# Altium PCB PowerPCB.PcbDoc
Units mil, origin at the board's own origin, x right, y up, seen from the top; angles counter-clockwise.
Board outline 7150 x 4890 mil, 2 copper layers (Top Layer, Bottom Layer); 59 components, 37 nets, 220 pads, 65 vias.
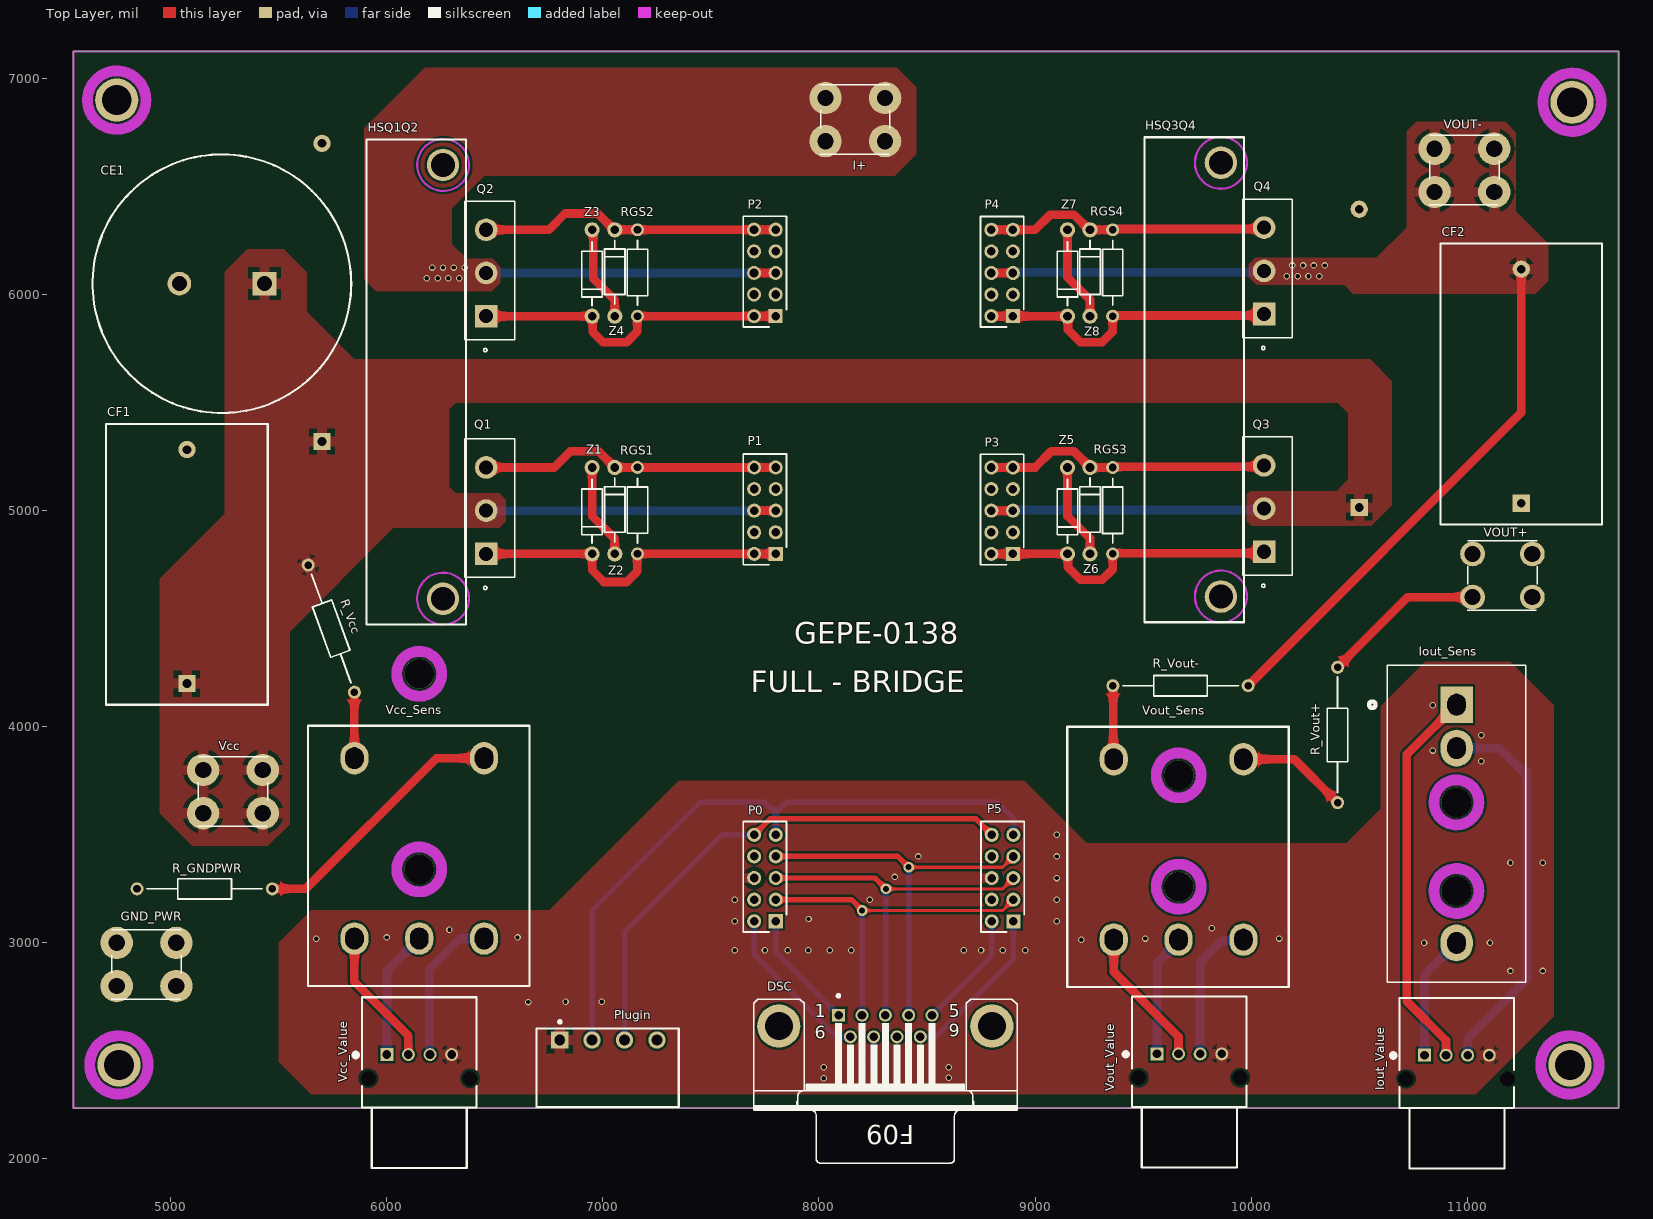
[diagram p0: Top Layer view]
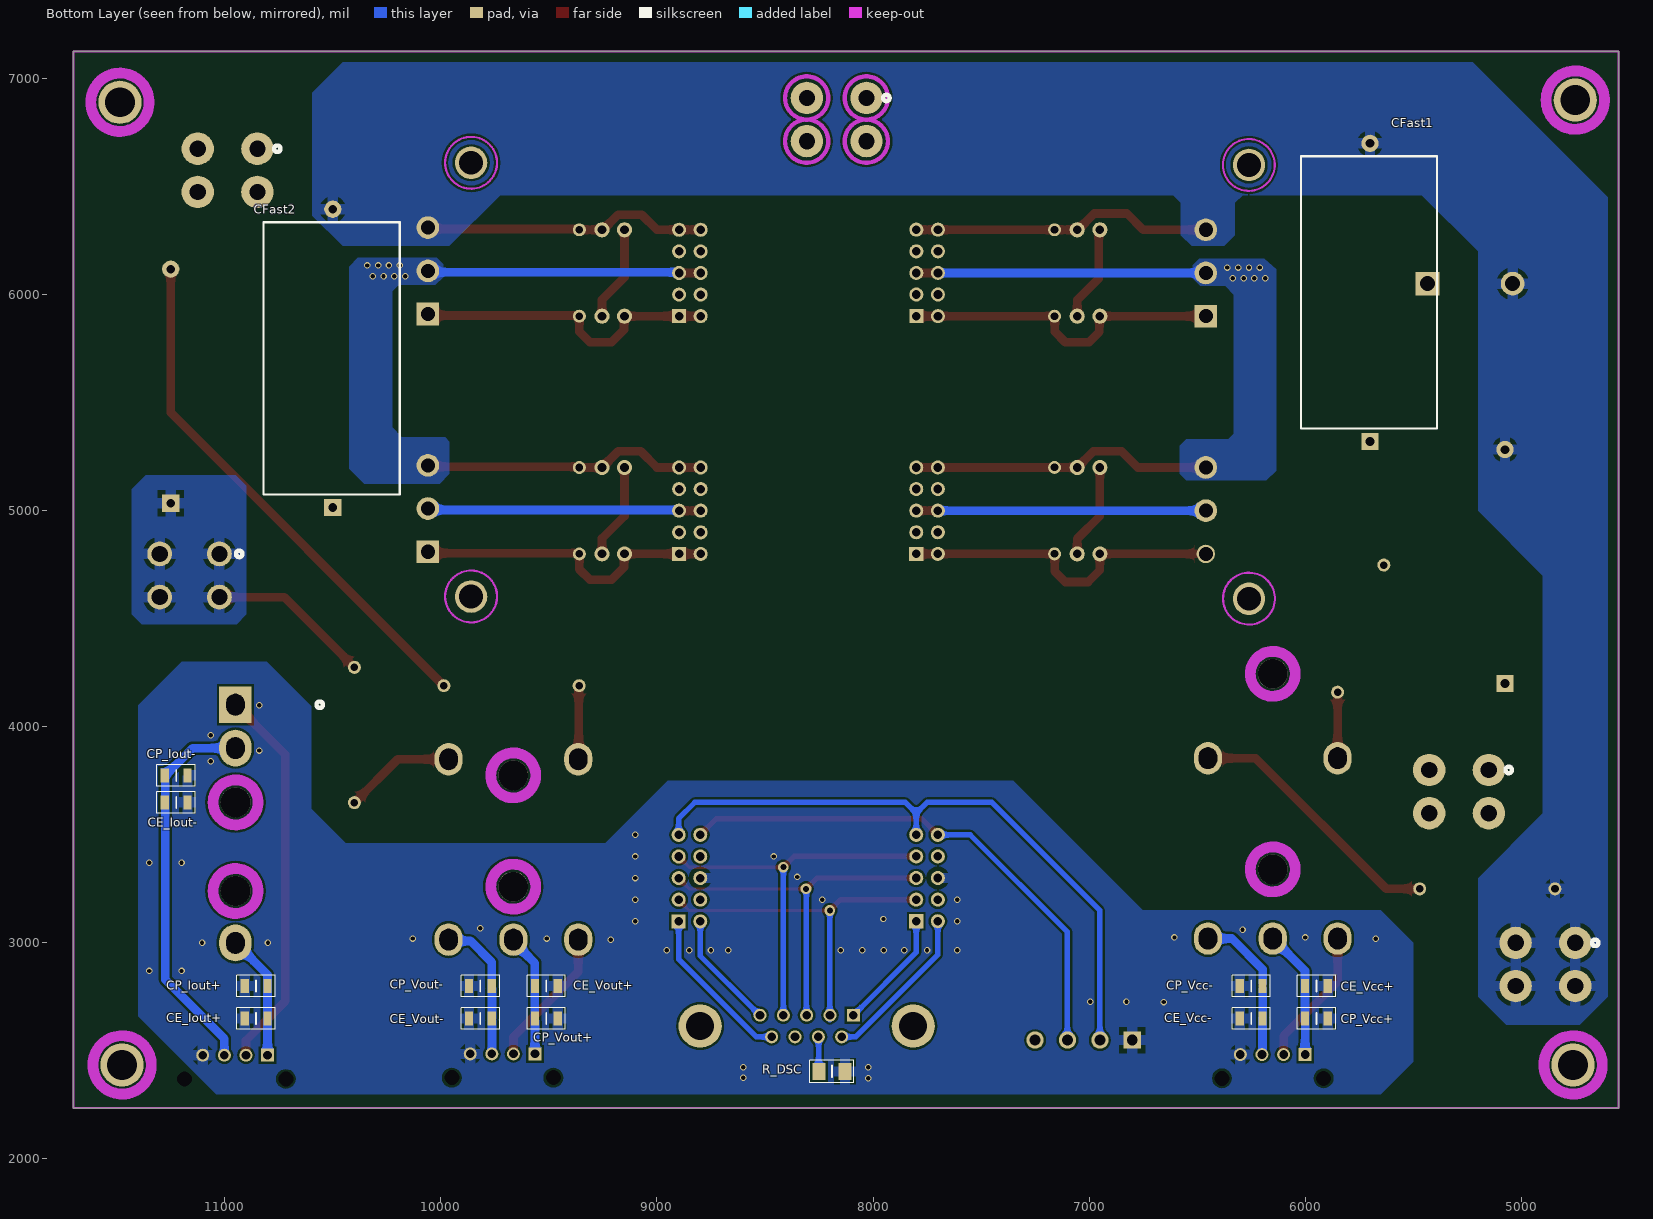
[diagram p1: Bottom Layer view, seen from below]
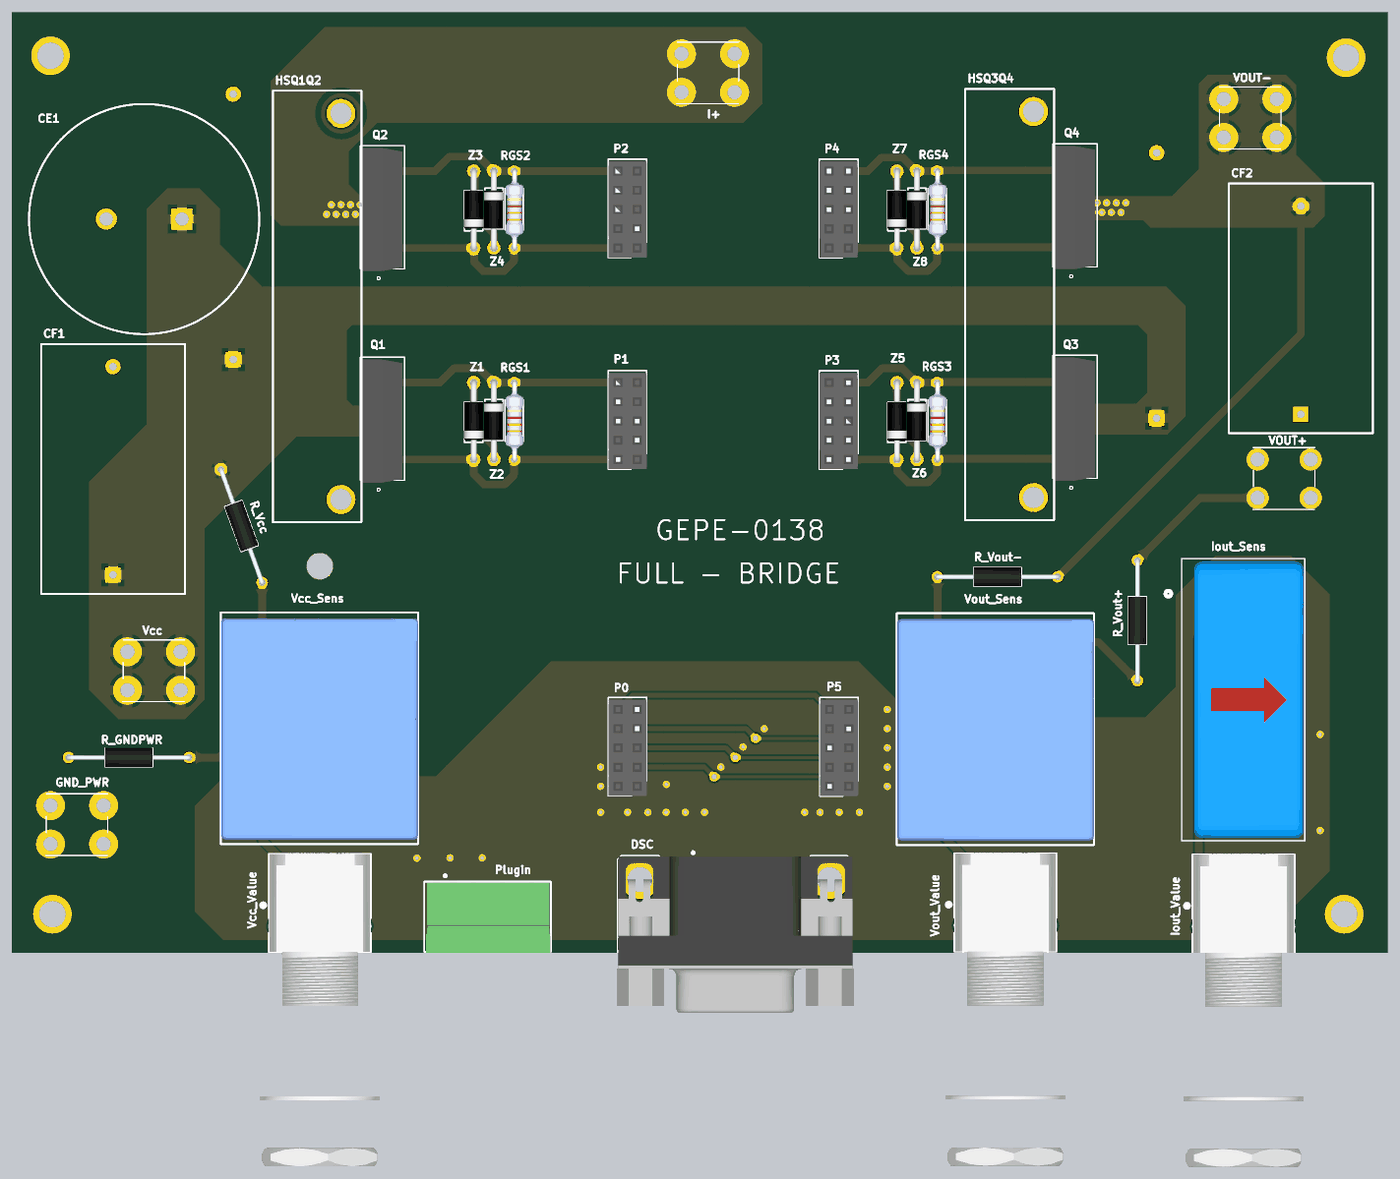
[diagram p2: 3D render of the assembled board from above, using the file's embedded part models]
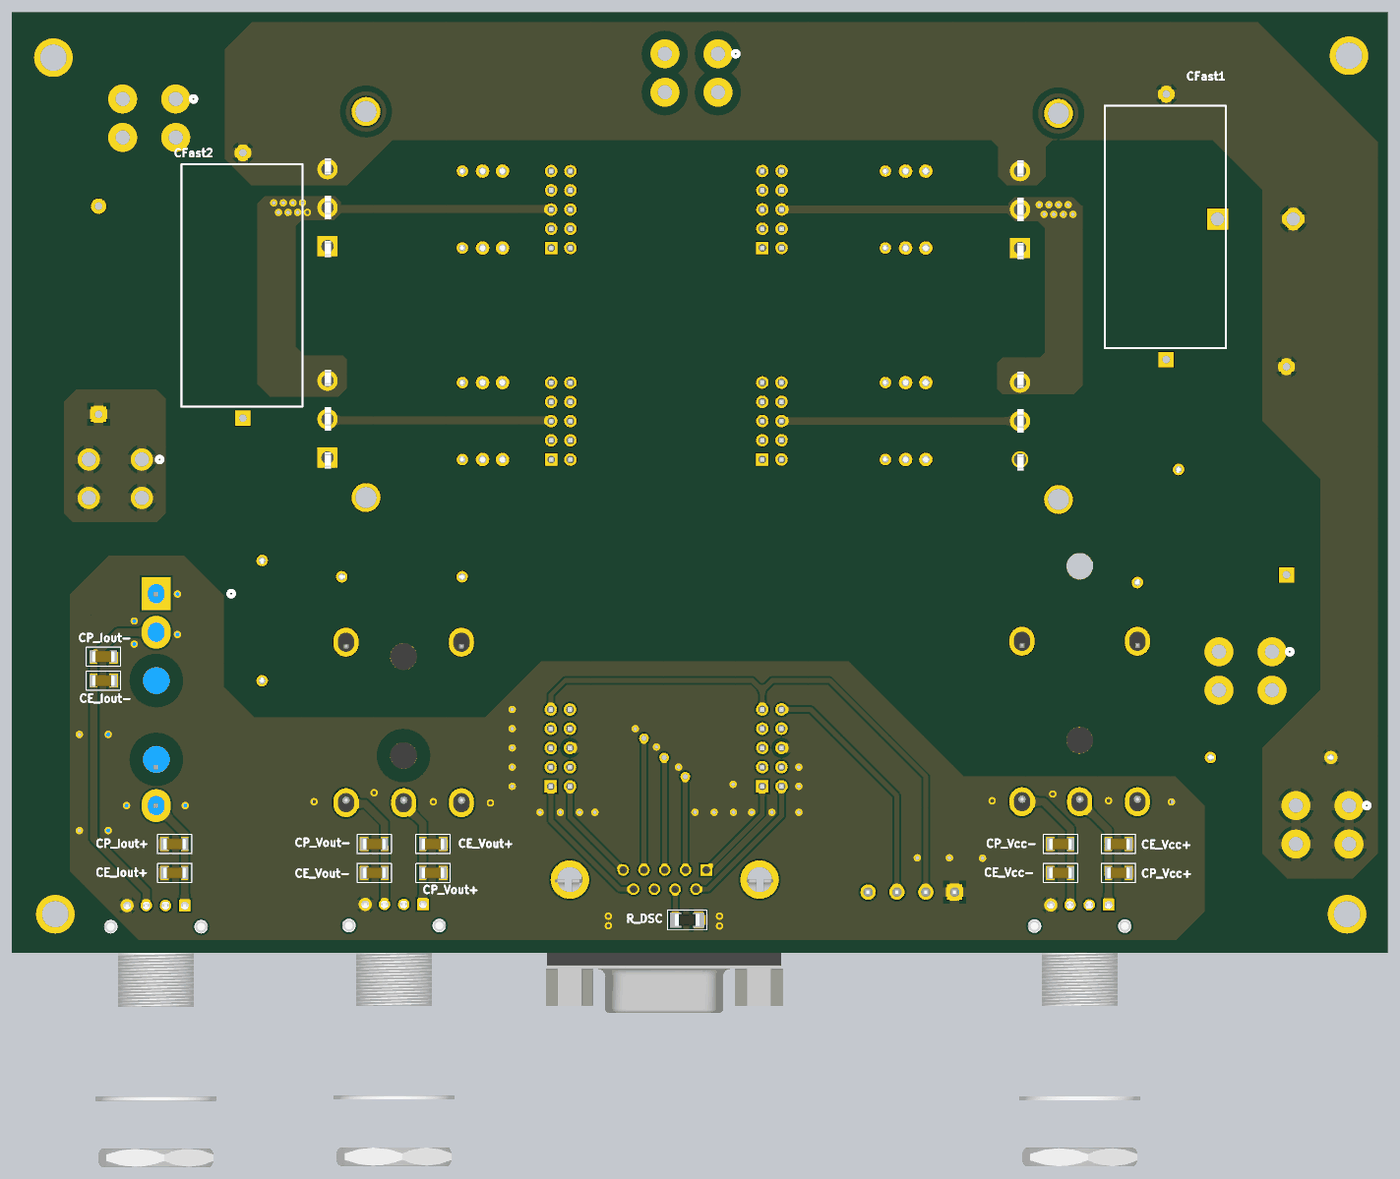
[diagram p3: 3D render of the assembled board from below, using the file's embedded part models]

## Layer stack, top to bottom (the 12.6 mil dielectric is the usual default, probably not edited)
Top Solder: solder mask 0.4, Solder Resist, Dk 3.5
Top Layer: signal copper 1.4
Dielectric 1: dielectric 12.6, FR-4, Dk 4.8
Bottom Layer: signal copper 1.4
Bottom Solder: solder mask 0.4, Solder Resist, Dk 3.5

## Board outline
4550,2235 11700,2235 11700,7125 4550,7125

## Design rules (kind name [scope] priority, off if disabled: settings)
Clearance Clearance_1 [All] p1: gap=10 ignorepadtopadclearanceinfootprint=TRUE
Clearance gnd_ISO_ [InNet('GND_ISO1') vs InNet('GND_PWR')] p2: gap=20 ignorepadtopadclearanceinfootprint=FALSE
ComponentClearance [All] p1: gap=-5 collisioncheckmode=3 verticalgap=-5 showdistances=FALSE
Height [All] p1: minheight=0 maxheight=5000 prefheight=2000
HoleSize [All] p1: absolutevalues=TRUE maxlimit=500 minlimit=1 maxpercent=80.000 minpercent=20.000
NetAntennae [All] p1: netantennaetolerance=10
PlaneClearance [All] p1: clearance=10
PolygonConnect [All] p1: connectstyle=Relief reliefconductorwidth=50 reliefentries=4 polygonreliefangle="90 Angle" airgapwidth=20
RoutingVias [All] p1: holewidth=28 width=50 viastyle="Through Hole" minholewidth=10 minwidth=10 maxholewidth=100 maxwidth=100
SilkToSilkClearance [All] p1: silktosilkclearance=5
SilkToSolderMaskClearance [IsPad] p1: minsilkscreentomaskgap=0 clearancetoexposedcopper=TRUE
SolderMaskExpansion [All] p1: expansion=4
Width [All] p1: maxlimit=180 minlimit=15 preferedwidth=40
23 further rules are at their usual default settings.

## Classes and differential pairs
component class Sensores: CE_Iout+ CE_Iout- CE_Vcc+ CE_Vcc- CE_Vout+ CE_Vout- CP_Iout+ CP_Iout- CP_Vcc+ CP_Vcc- CP_Vout+ CP_Vout- Iout_Sens R_GNDPWR R_Vcc R_Vout+ R_Vout- Vcc_Sens Vout_Sens
component class PowerPCB: CE1 CF1 CF2 CFast1 CFast2 DSC GND_PWR HSQ1Q2 HSQ3Q4 I+ Iout_Value P0 P1 P2 P3 P4 P5 Plugin Q1 Q2 Q3 Q4 R_DSC RGS1 RGS2 RGS3 RGS4 Vcc Vcc_Value VOUT+ VOUT- Vout_Value x Z1 Z2 Z3 Z4 Z5 Z6 Z7 Z8

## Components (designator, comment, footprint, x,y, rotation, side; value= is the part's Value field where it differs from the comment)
CE1 "CAP" CAP_ELETRO 5433.54,6050.5 r180 top
CE_Iout+ "CAP" CAP3115_SMD 10855,2650 r0 bottom
CE_Iout- "CAP" CAP3115_SMD 11225,3650 r180 bottom
CE_Vcc+ "CAP" CAP3115_SMD 5948,2800 r180 bottom
CE_Vcc- "CAP" CAP3115_SMD 6250,2650 r0 bottom
CE_Vout+ "CAP" CAP3115_SMD 9512,2800 r180 bottom
CE_Vout- "CAP" CAP3115_SMD 9817,2650 r0 bottom
CF1 "CAP" CAP_MKP1848C61050JK2 5075,4200 r90 top
CF2 "CAP" CAP_MKP1848C61050JK2 11250,5035 r90 top
CFast1 "CAP" CAP_FAST 5700,5320 r90 bottom
CFast2 "CAP" CAP_FAST 10500,5015 r90 bottom
CP_Iout+ "CAP" CAP3115_SMD 10855,2800 r0 bottom
CP_Iout- "CAP" CAP3115_SMD 11225,3775 r180 bottom
CP_Vcc+ "CAP" CAP3115_SMD 5948,2650 r180 bottom
CP_Vcc- "CAP" CAP3115_SMD 6250,2800 r0 bottom
CP_Vout+ "CAP" CAP3115_SMD 9512,2650 r180 bottom
CP_Vout- "CAP" CAP3115_SMD 9817,2800 r0 bottom
DSC "Con_DB9" CON_DB9_FEMALE 8520,2665 r0 top
GND_PWR "8191" CONN_8191_KEY#1 4750,3000 r0 top
HSQ1Q2 "Heat_Sinks_TO247" HEAT_SINKS_TO247 6260,4592.13 r90 top
HSQ3Q4 "Heat_Sinks_TO247" HEAT_SINKS_TO247 9860,4602.13 r90 top
I+ "8191" CONN_8191_KEY#1 8030,6910 r0 top
Iout_Sens "LA100P" LA100P 10950,4100 r0 top
Iout_Value "Con_MiniXLR_TRAPC4M" CON_MINIXLR_TRAPC4M1X 10802,2480 r0 top
P0 "Header 5X2" HEADER_FEM_TH_10P_2.54 7700,3100 r90 top
P1 "Header 5X2" HEADER_FEM_TH_10P_2.54 7699.85,4800.12 r90 top
P2 "Header 5X2" HEADER_FEM_TH_10P_2.54 7699.53,5900.26 r90 top
P3 "Header 5X2" HEADER_FEM_TH_10P_2.54 8797.44,4799.87 r90 top
P4 "Header 5X2" HEADER_FEM_TH_10P_2.54 8797.44,5900 r90 top
P5 "Header 5X2" HEADER_FEM_TH_10P_2.54 8799.44,3099.74 r90 top
Plugin "Con_4Pin_Horizontal_plugin_3.81mm" 691322310004 6800,2550 r0 top
Q1 "LSIC1MO120E0080" SICMOSFET#1 6460,4800 r90 top
Q2 "LSIC1MO120E0080" SICMOSFET#2 6460,5900 r90 top
Q3 "LSIC1MO120E0080" SICMOSFET#2 10060,4810 r90 top
Q4 "LSIC1MO120E0080" SICMOSFET#2 10060,5910 r90 top
R_DSC "Res1" RESIS_SMD_1206 8190,2405 r0 bottom
R_GNDPWR "Res1" RESIS_TH_15.9 4844.02,3250 r0 top
R_Vcc "Res1" RESIS_TH_15.9 5635.9,4748.23 r290 top
R_Vout+ "Res1" RESIS_TH_15.9 10400,4275 r270 top
R_Vout- "Res1" RESIS_TH_15.9 9985.98,4190 r180 top
RGS1 "Res1" RESIS_TH_10.1 7160,5200 r270 top
RGS2 "Res1" RESIS_TH_10.1 7160,6300 r270 top
RGS3 "Res1" RESIS_TH_10.1 9359.01,5199.75 r270 top
RGS4 "Res1" RESIS_TH_10.1 9359.01,6300 r270 top
Vcc "8191" CONN_8191_KEY#1 5150,3800 r0 top
Vcc_Sens "Volt_Sens" VOLT_SENS 5850,3020 r0 top
Vcc_Value "Con_MiniXLR_TRAPC4M" CON_MINIXLR_TRAPC4M1X 6000,2483 r0 top
VOUT+ "8191" CONN_8191_KEY#2 11025,4800 r0 top
VOUT- "8191" CONN_8191_KEY#1 10849,6675 r0 top
Vout_Sens "Volt_Sens" VOLT_SENS 9364,3015 r0 top
Vout_Value "Con_MiniXLR_TRAPC4M" CON_MINIXLR_TRAPC4M1X 9564,2486 r0 top
Z1 "TLHR5400-AS12Z" DIODE_TH_10.1 6950,4800 r90 top
Z2 "TLHR5400-AS12Z" DIODE_TH_10.1 7055,5200 r270 top
Z3 "TLHR5400-AS12Z" DIODE_TH_10.1 6950,5900 r90 top
Z4 "TLHR5400-AS12Z" DIODE_TH_10.1 7055,6300 r270 top
Z5 "TLHR5400-AS12Z" DIODE_TH_10.1 9150,4799.87 r90 top
Z6 "TLHR5400-AS12Z" DIODE_TH_10.1 9254,5199.87 r270 top
Z7 "TLHR5400-AS12Z" DIODE_TH_10.1 9150,5900 r90 top
Z8 "TLHR5400-AS12Z" DIODE_TH_10.1 9254,6300 r270 top

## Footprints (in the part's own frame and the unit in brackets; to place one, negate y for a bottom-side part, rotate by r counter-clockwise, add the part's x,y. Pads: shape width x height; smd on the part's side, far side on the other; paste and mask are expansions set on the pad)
691322310004 [mil] "WR-TBL Series 322 - 3.81 mm Horizontal PCB Header"
  rect 80x80 hole 50: 1(0,0)
  round 80 hole 50: 2(150,0) 3(300,0) 4(450,0)
  silkscreen extent -107,-310 551,91, body extent -97,-315 549,47, height 295
CAP3115_SMD [mm]
  rect 0.96x1.64 smd: 1(-1.34,0) 2(1.34,0)
  silkscreen extent -2.26,-1.25 2.25,1.25, body extent -1.55,-0.75 1.55,0.75, height 1.8
CAP_ELETRO [mil] "Nichicon_LGL"
  rect 110x110 hole 70: 1(0,0)
  round 110 hole 70: 2(393.7,0)
  silkscreen extent -402,-598 795,598, body extent -394,-590 787,590, height 984
CAP_FAST [mil] "LCR PC/HV/S/WF 100nF"
  rect 80x80 hole 40: 1(0,0)
  round 80 hole 40: 2(1380,0)
  silkscreen extent 60,-310 1320,320, body extent -20,-315 1400,325, height 670
CAP_MKP1848C61050JK2 [mil] "MKP1848C61050JK2"
  rect 80x80 hole 40: 1(0,0)
  round 80 hole 40: 2(1082.68,0)
  silkscreen extent -98,-374 1201,374, body extent -79,-354 1181,359, height 984
CON_DB9_FEMALE [mil] "Connector; D Subminiature; 9 Position; Right Angle; Pitch 1.385 mm"
  rect 60x60 hole 40: 1(-429,0)
  round 60 hole 40: 2(-321,0) 3(-213,0) 4(-105,0) 5(3,0) 6(-375,-100) 7(-267,-100) 8(-159,-100) 9(-51,-100)
  round 200 hole 130: 10(-706,-50) 10(280,-50)
  silkscreen extent -823,-684 398,96, body extent -825,-742 405,69, height 493
CON_MINIXLR_TRAPC4M1X [mil]
  rect 60x60 hole 40: 1(0,0)
  round 60 hole 40: 2(200,0) 3(300,0) 4(100,0)
  round 35 hole 70 unplated: MH1(-85,-110) MH2(385,-110)
  silkscreen extent -144,-525 415,265, body extent -162,-1359 462,271, height 105
CONN_8191_KEY#1 [mil]
  round 150 hole 75 mask+0: 1(0,0) 2(276,0) 3(0,-200) 4(276,-200)
  silkscreen extent -25,-260 298,62
CONN_8191_KEY#2 [mil]
  round 115 hole 75 mask+0: 1(0,0) 2(276,0) 3(0,-200) 4(276,-200)
  silkscreen extent -25,-260 298,62
DIODE_TH_10.1 [mil]
  round 70 hole 40: 1(0,0) 2(400,0)
  silkscreen extent 49,-47 345,47, body extent -15,-51 415,50, height 100
HEADER_FEM_TH_10P_2.54 [mil]
  rect 65x65 hole 40: 1(0,-100)
  round 65 hole 40: 2(0,0) 3(100,-100) 4(100,0) 5(200,-100) 6(200,0) 7(300,-100) 8(300,0) 9(400,-100) 10(400,0)
  silkscreen extent -50,-150 462,50, body extent -50,-150 450,50, height 335
HEAT_SINKS_TO247 [mm] "VRA-55-101E"
  round 3.81 hole 2.8 unplated: 1(0,0) 2(51,0)
  silkscreen extent -3,-2.7 54,9, body extent -3,-25 54,9, height 39.5
LA100P [mil]
  rect 150x170 hole 85 slot 100 at 90 deg mask+0: 1(0.58,2.07)
  oval 150x170 hole 85 slot 100 at 90 deg mask+0: 2(0.58,-198.71) 3(0.58,-1100.29)
  silkscreen extent -404,-1283 321,184, body extent -254,-1269 314,169, height 1085
RESIS_SMD_1206 [mil]
  rect 60x80 smd: 1(-60,0) 2(60,0)
  silkscreen extent -102,-52 102,52, body extent -63,-31 63,31, height 30
RESIS_TH_10.1 [mil]
  round 60 hole 35: 1(0,0) 2(400,0)
  silkscreen extent 50,-47 350,47, body extent -12,-45 412,49, height 95
RESIS_TH_15.9 [mil]
  round 60 hole 35: 1(0,0) 2(625.98,0)
  silkscreen extent 45,-47 580,47, body extent -12,-49 638,49, height 98
SICMOSFET#1 [mil]
  rect 105x105 / inner round 85 / far side round 85 hole 65 mask+0: 1(0,0)
  round 105 hole 65 mask+0: 2(200,0) 3(400,0)
  silkscreen extent -165,-131 532,99, body extent -120,-120 520,89, height 961
SICMOSFET#2 [mil]
  rect 105x105 hole 65 mask+0: 1(0,0)
  round 105 hole 65 mask+0: 2(200,0) 3(400,0)
  silkscreen extent -165,-131 532,99, body extent -120,-120 520,89, height 961
VOLT_SENS [mil]
  oval 130x150 hole 85 slot 100 at 90 deg: 1(0,834.6) 2(600,834.6) 3(0,0) 4(300,0) 5(600,0)
  silkscreen extent -215,-220 810,985, body extent -213,-195 811,954, height 658

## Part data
CE1 CE_Iout+ CE_Iout- CE_Vcc+ CE_Vcc- CE_Vout+ CE_Vout- CF1 CF2 CFast1 CFast2 CP_Iout+ CP_Iout- CP_Vcc+ CP_Vcc- CP_Vout+ CP_Vout-: "Capacitor", Manufacturer_Name=Kemet, Manufacturer_Part_Number=C1206X475K3RACAUTO7210, Mouser Part Number=80-C1206X475K3RAUTLR
DSC: "DB9 (Right angle  PCB mount)", ASiD Part Number=DB9-AS
GND_PWR I+ Vcc VOUT+ VOUT-: "No Description Available", Mfr_Name="Keystone Electronics"
Iout_Value Vcc_Value Vout_Value: "Connector", Arrow Part Number=TRAPC4M1X, Manufacturer_Name=Switchcraft, Mouser Part Number=502-TRAPC4M1X
P0 P1 P2 P3 P4 P5: library part Con_Header_10P, "Connector dual row"
Plugin: "691322310004 WE"
Q1 Q2 Q3 Q4: library part SICMOS
R_DSC R_GNDPWR R_Vcc R_Vout+ R_Vout- RGS1 RGS2 RGS3 RGS4: library part Resistor, "Resistor"
Z1 Z2 Z3 Z4 Z5 Z6 Z7 Z8: library part Diode, "Diode", Manufacturer_Name=Vishay

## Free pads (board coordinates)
  round 200 hole 137.8 mask+0: 1(4750,6900) 1(4760,2435) 1(11475,2435) 1(11485,6890)
  round 137.8 hole 137.8 mask+0: 1(6150,3340) 1(6150,4245) 1(9665,3260) 1(9665,3775) 1(10950,3240) 1(10950,3650)

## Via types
v1: diameter 30, hole 20, Top Layer to Bottom Layer, 62 vias
v2: diameter 50, hole 28, Top Layer to Bottom Layer, 3 vias

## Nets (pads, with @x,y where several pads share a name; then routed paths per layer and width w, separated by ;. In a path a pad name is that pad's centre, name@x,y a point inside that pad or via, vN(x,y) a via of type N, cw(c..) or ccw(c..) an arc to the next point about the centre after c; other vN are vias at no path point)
GND: CE_Iout+.2 CE_Iout-.2 CE_Vcc+.2 CE_Vcc-.2 CE_Vout+.2 CE_Vout-.2 CP_Iout+.2 CP_Iout-.2 CP_Vcc+.2 CP_Vcc-.2 CP_Vout+.2 CP_Vout-.2 Iout_Value.3 P0.6 P5.6 Plugin.1 R_DSC.1 Vcc_Value.3 Vout_Value.3
  other v1: 8022,2374 8600,2375 8022,2425 8600,2425 6655,2726 6827,2728 6994,2728 11200,2870 11350,2870 7610,2965 7750,2965 7855,2965 7950,2965 8050,2965 8150,2965 8670,2965 8750,2965 8850,2965 8955,2965 10800,3000 11105,3000 9213,3014 5673,3019 9510,3020 10130,3020 6000,3025 6605,3025 6290,3060 9818,3067 7610,3100 9100,3100 7951.78,3110.36 7610,3200 8235,3200 9100,3200 9100,3300 8350,3305 11200,3370 11350,3370 8460,3400 9100,3400 9100,3500 11065,3840 10840,3890 11065,3960 10840,4100
GND_ISO1: I+.1 I+.2 I+.3 I+.4 P1.9 P1.10 P2.5 P2.6 Q1.3 Q2.2 RGS1.1 Z2.1 | length 2762.1
  Top Layer w40: Q1.3@6450,5200 6775,5200 6850,5275 6980,5275 Z2.1 RGS1.1 7160.06,5200.06 P1.10 P1.10 P1.9 ; P2.6 P2.5 7799.74,6100.26 P2.5@7800,6100
  Bottom Layer w40: Q2.2@6450.13,6100.13 7699.4,6100.13 P2.6
  other v1: 6185,6075 6235,6075 6285,6075 6335,6075 6210,6125 6260,6125 6310,6125 6360,6125
GND_ISO2: CF2.2 P3.9 P3.10 P4.5 P4.6 Q3.3 Q4.2 R_Vout-.1 RGS3.1 VOUT-.1 VOUT-.2 VOUT-.3 VOUT-.4 Z6.1 | length 5020.5
  Top Layer w40: P3.10 P3.9 8999.87,5199.87 9075,5275 9178.87,5275 Z6.1 9254.06,5199.81 RGS3.1 RGS3.1 9362.64,5203.38 10046.35,5203.38 Q3.3@10051.12,5208.15 ; P4.6 P4.5 ; R_Vout-.1 11250,5454.02 CF2.2@11250,6117
  Bottom Layer w40: P4.5@8900.94,6103.5 10046.5,6103.5 Q4.2@10050,6107
  other v1: 10165,6085 10215,6085 10265,6085 10315,6085 10190,6135 10240,6135 10290,6135 10340,6135
GND_PWR: CE1.2 CF1.2 CFast1.2 CFast2.2 GND_PWR.1 GND_PWR.2 GND_PWR.3 GND_PWR.4 P2.9 P2.10 P4.9 P4.10 Q2.3 Q4.3 R_GNDPWR.1 RGS2.1 RGS4.1 Z4.1 Z8.1 | length 2727.1
  Top Layer w40: Q2.3@6450,6300 6750,6300 6825,6375 6975.65,6375 7053.07,6297.58 Z4.1@7054.89,6297.58 ; Z4.1 7159.74,6300 RGS2.1@7160.03,6299.71 ; RGS2.1 7160.13,6300.13 7699.4,6300.13 P2.10 P2.9 ; P4.10 P4.9@8898.26,6300 ; P4.9 9000,6300 9070,6370 9179.65,6370 9249.65,6300 RGS4.1 9362.51,6303.5 10046.5,6303.5 Q4.3@10050,6307
NetCE1_1: CE1.1 CF1.1 CFast1.1 CFast2.1 P1.5 P1.6 P3.5 P3.6 Q1.2 Q3.2 R_Vcc.1 Vcc.1 Vcc.2 Vcc.3 Vcc.4 | length 2616.7
  Top Layer w40: P1.6 P1.5 ; P3.6 P3.5
  Bottom Layer w40: Q1.2@6450,5000 6450.06,5000.06 P1.6 P1.6 ; P3.5 8901.01,5003.43 10053.43,5003.43 Q3.2
NetCE_Iout+_1: CE_Iout+.1 CP_Iout+.1 Iout_Sens.3 Iout_Value.1 | length 581.3
  Bottom Layer w40: Iout_Value.1 10802.12,2480.12 10802.12,2637.72 10802.24,2637.84 CE_Iout+.1 10802.24,2852.24 Iout_Sens.3@10950,3000
NetCE_Iout-_1: CE_Iout-.1 CP_Iout-.1 Iout_Sens.2 Iout_Value.2 | length 1785.9
  Bottom Layer w40: Iout_Sens.2@10950,3900 10951.29,3901.29 11148.71,3901.29 11275,3775 11275,3650 11275,2830 11002,2557 Iout_Value.2
NetCE_Vcc+_1: CE_Vcc+.1 CP_Vcc+.1 Vcc_Sens.4 Vcc_Value.1 | length 599.1
  Bottom Layer w40: Vcc_Value.1 6000.38,2483.38 6000.38,2637.72 6000.76,2638.09 CP_Vcc+.1 CE_Vcc+.1 6000.76,2870.76 Vcc_Sens.4
NetCE_Vcc-_1: CE_Vcc-.1 CP_Vcc-.1 Vcc_Sens.5 Vcc_Value.2 | length 667.2
  Bottom Layer w40: CE_Vcc-.1@6197.09,2662.28 CP_Vcc-.1@6197.09,2787.72 ; CP_Vcc-.1@6197.09,2812.28 6197.09,2878.09 6339,3020 Vcc_Sens.5 ; Vcc_Value.2@6197.24,2485.75 CE_Vcc-.1
NetCE_Vout+_1: CE_Vout+.1 CP_Vout+.1 Vout_Sens.4 Vout_Value.1 | length 570.8
  Bottom Layer w40: Vout_Value.1 9564.38,2486.38 9564.38,2637.72 9564.76,2638.09 CP_Vout+.1 CE_Vout+.1 9564.76,2905.76 9665,3006 Vout_Sens.4@9665,3015
NetCE_Vout-_1: CE_Vout-.1 CP_Vout-.1 Vout_Sens.5 Vout_Value.2 | length 642.4
  Bottom Layer w40: Vout_Value.2@9763.14,2486.86 CE_Vout-.1@9763.14,2637.72 ; CP_Vout-.1@9763.14,2787.72 9763.14,2651.1 CE_Vout-.1 ; CP_Vout-.1 9764.24,2910.24 9863.11,3009.11 9958.11,3009.11 Vout_Sens.5
NetCF2_1: CF2.1 R_Vout+.1 VOUT+.1 VOUT+.2 VOUT+.3 VOUT+.4 | length 759.6
  Top Layer w40: R_Vout+.1 10725,4600 VOUT+.3
NetDSC_1: DSC.1 P0.1 | length 555.5
  Bottom Layer w25: P0.1 7800,2956 DSC.1
NetDSC_2: DSC.2 P0.3 P5.3 | length 1646.7
  Top Layer w15: v2(8200,3150) 8200.26,3149.74 8449.44,3149.74 ; 8450,3150 8450.26,3149.74 8849.44,3149.74 P5.3 8899.7,3200 P5.3@8900,3200
  Top Layer w25: P0.3 8150,3200 v2(8200,3150)
  Bottom Layer w25: DSC.2@8200,2644.5 v2(8200,3150)
NetDSC_3: DSC.3 P0.5 P5.5 | length 1736.1
  Top Layer w15: v2@8300,3250 8300.26,3249.74 8849.44,3249.74 P5.5 8899.7,3300 P5.5@8900,3300
  Top Layer w25: P0.5 8260,3300 v2(8310,3250) ; v2@8300,3250 v2@8300,3253.24
  Bottom Layer w25: DSC.3@8310,2670 8308.5,2671.5 8308.5,3248.5 v2(8310,3250)
NetDSC_4: DSC.4 P0.7 P5.7 | length 1819.7
  Top Layer w15: v2@8420,3350 8420.26,3349.74 8849.44,3349.74 8894.7,3395 P5.7@8905,3395
  Top Layer w25: P0.7 8365,3400 v2(8415,3350)
  Bottom Layer w25: DSC.4 8415,3338.24 8414.78,3338.45 8414.78,3344.78 v2@8415,3345
NetDSC_5: DSC.5 P5.2 | length 549.6
  Bottom Layer w25: DSC.5@8525,2665 8525,2667 8540.5,2682.5 8542.5,2682.5 8799.44,2939.44 8799.44,2999.74 ; P5.2 8799.44,3000.56 8800,3000
NetDSC_6: DSC.6 P0.2 | length 757.4
  Bottom Layer w25: P0.2 7700,2945 8080,2565 DSC.6
NetDSC_7: DSC.7 R_DSC.2 | length 166.2
  Bottom Layer w25: R_DSC.2@8250,2400 8251.5,2401.5 8251.5,2563.5 DSC.7
NetDSC_9: DSC.9 P5.1 | length 755.4
  Bottom Layer w25: DSC.9@8470,2560 8475,2565 8540,2565 8899.44,2924.44 8899.44,2999.44 ; P5.1 8899.44,3000.56 8900,3000
NetIout_Sens_1: Iout_Sens.1 Iout_Value.4 | length 1792.1
  Top Layer w40: Iout_Value.4 10902,2548 10720,2730 10720,3871.49 Iout_Sens.1@10950,4101.49
NetP0_9: P0.9 P5.9 Plugin.2 | length 3010.9
  Top Layer w25: P0.9 P0.9@7800.13,3499.87 ; P5.9@8893.88,3500 P5.9@8900,3500
  Bottom Layer w25: Plugin.2 6950,3150 7450,3650 7750,3650 7800,3600 ; P0.9 7800,3600 ; P5.9 8899.44,3575.56 8825,3650 7850,3650 7800,3600
NetP0_10: P0.10 P5.10 Plugin.3 | length 2454.9
  Top Layer w25: P0.10@7705.81,3500 P0.10 7775,3575 8725,3575 P5.10@8800,3500
  Bottom Layer w25: Plugin.3@7101,2549 7101,3051 7550,3500 P0.10
NetP1_1: P1.1 P1.2 Q1.1 RGS1.2 Z1.1 | length 1546.9
  Top Layer w40: Q1.1@6450,4800 Z1.1 6950,4725 7005,4670 7110,4670 7158.95,4718.95 RGS1.2@7158.95,4798.95 ; RGS1.2@7160,4800.06 P1.2 P1.2 P1.1
NetP2_1: P2.1 P2.2 Q2.1 RGS2.2 Z3.1 | length 1527
  Top Layer w40: Q2.1@6450,5900 Z3.1 ; Z3.1@6952.24,5897.62 6952.24,5827.76 7000,5780 7110,5780 7159.01,5829.01 RGS2.2@7159.01,5899.75 ; RGS2.2@7160.13,5900.13 7699.4,5900.13 P2.2 ; P2.2@7694.44,5900 P2.1@7794.57,5900
NetP3_1: P3.1 P3.2 Q3.1 RGS3.2 Z5.1 | length 1426.2
  Top Layer w40: P3.2 P3.1 Z5.1 9152.24,4797.62 9152.24,4737.76 9210,4680 9310,4680 9359.01,4729.01 RGS3.2 ; RGS3.2@9362.64,4803.38 10046.38,4803.38 Q3.1@10050,4807
NetP4_1: P4.1 P4.2 Q4.1 RGS4.2 Z7.1 | length 1432.4
  Top Layer w40: P4.2 P4.1 Z7.1 Z7.1@9154.35,5900 ; Z7.1@9152.24,5897.62 9152.24,5837.76 9210,5780 9310,5780 9359.01,5829.01 RGS4.2@9359.01,5899.75 ; RGS4.2 9362.51,5903.5 10046.5,5903.5 Q4.1@10050,5907
NetR_GNDPWR_2: R_GNDPWR.2 Vcc_Sens.2 | length 1232.3
  Top Layer w40: R_GNDPWR.2 5625,3250 6229.6,3854.6 6445.4,3854.6 Vcc_Sens.2@6450,3850
NetR_Vcc_2: R_Vcc.2 Vcc_Sens.1 | length 312
  Top Layer w40: Vcc_Sens.1 R_Vcc.2@5850,4166.57
NetR_Vout+_2: R_Vout+.2 Vout_Sens.2 | length 539.7
  Top Layer w40: Vout_Sens.2 10170.4,3849.6 ; 10150,3850 10199.02,3850 R_Vout+.2
NetR_Vout-_2: R_Vout-.2 Vout_Sens.1 | length 342.1
  Top Layer w40: R_Vout-.2 9362,4188 9362,3851.6 Vout_Sens.1
NetVcc_Sens_3: Vcc_Sens.3 Vcc_Value.4 | length 640.6
  Top Layer w40: Vcc_Sens.3 5850,2820 6100,2570 Vcc_Value.4
NetVout_Sens_3: Vout_Sens.3 Vout_Value.4 | length 653.3
  Top Layer w40: Vout_Sens.3 9364,2866 9664,2566 Vout_Value.4
NetZ1_2: Z1.2 Z2.2 | length 443.5
  Top Layer w40: Z1.2 6950,4975 7055,4870 Z2.2
NetZ3_2: Z3.2 Z4.2 | length 443.5
  Top Layer w40: Z3.2 6955.74,6294.26 6955.74,6074.26 7055,5975 Z4.2
NetZ5_2: Z5.2 Z6.2 | length 443.1
  Top Layer w40: Z5.2 9150,4975 9254,4871 Z6.2
NetZ7_2: Z7.2 Z8.2 | length 443.1
  Top Layer w40: Z7.2 9150,6080 9254,5976 Z8.2
pads on no net: DSC.8 DSC.10 HSQ1Q2.1 HSQ1Q2.2 HSQ3Q4.1 HSQ3Q4.2 Iout_Value.MH1 Iout_Value.MH2 P0.4 P0.8 P1.3 P1.4 P1.7 P1.8 P2.3 P2.4 P2.7 P2.8 P3.3 P3.4 P3.7 P3.8 P4.3 P4.4 P4.7 P4.8 P5.4 P5.8 Plugin.4 Vcc_Value.MH1 Vcc_Value.MH2 Vout_Value.MH1 Vout_Value.MH2

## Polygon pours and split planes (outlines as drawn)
NetCE1_1 on Top Layer "NETCE1_1_L01_P046" (solid, pour order 46): 5100,3450 5450,3450 5550,3550 5550,4440 6030,4920 6520,4920 6550,4950 6550,5050 6520,5080 6320.02,5080 6290,5110.02 6290,5470 6320,5500 10400,5500 10450,5450 10450,5145 10395.01,5090.01 9995,5090.01 9980,5075.01 9980,4950 10000,4930 10555,4930 10650,5025 10650,5600 10550,5700 9600,5700 5850,5700 5630,5920 5630,6103 5523,6210 5355,6210 5250,6105 5250,4985 4950,4685 4950,3600
GND on Top Layer "GND_L01_P056" (solid, pour order 56): 11040,2300 11400,2660 11400,4100 11200,4300 10805,4300 10600,4095 10600,3620 10440.19,3460.19 9239.53,3460.19 8950.31,3750 7350,3750 6751,3151 5650.79,3151 5500,3000.21 5500,2450 5650,2300
GND_ISO2 on Top Layer "GND_ISO2_L01_P047" (solid, pour order 47): 10765,6800 10720,6755 10720,6310 10580,6170 10020,6170 9990,6140 9990,6080 10025,6045 10430,6045 10470,6005 11315,6005 11375,6065 11375,6235 11225,6385 11225,6750 11175,6800
GND_ISO1 on Top Layer "GND_ISO1_L01_P053" (solid, pour order 53): 8450,6650 8350,6550 7380,6550 6450,6550 6300,6400 6300,6233.94 6368.94,6165 6490,6165 6525,6130 6525,6055 6485,6015 5950,6015 5895,6070 5895,6770 6175,7050 8360,7050 8450,6960
GND on Bottom Layer "GND_L02_P055" (solid, pour order 55): 11040,2300 11400,2660 11400,4100 11200,4300 10805,4300 10600,4095 10600,3620.49 10440.26,3460 9240,3460 8950,3750 7350,3750 6751,3151 5651,3151 5500,3000 5500,2450 5650,2300
GND_ISO2 on Bottom Layer "GND_ISO2_L02_P050" (solid, pour order 50): 10025,6045 9990,6080 9990,6140 10020,6170 10385,6170 10425,6130 10425,5195 10355,5125 10005,5125 9960,5170 9960,5320 9980,5340 10180,5340 10225,5385 10225,6015 10195,6045 10030,6045
GND_ISO1 on Bottom Layer "GND_ISO1_L02_P051" (solid, pour order 51): 6485,6040 6520,6075 6520,6135 6490,6165 6188.81,6165 6135,6117.25 6135,5185 6180,5140 6550,5140 6580,5170 6580,5300 6550,5330 6355,5330 6330,5355 6330,6000 6370,6040
NetCF2_1 on Bottom Layer "NETCF2_1_L02_P049" (solid, pour order 49): 10950,5165 10900,5115 10900,4520 10945,4475 11385,4475 11430,4520 11430,5100 11365,5165
GND_PWR on Bottom Layer "GND_PWR_L02_P045" (solid, pour order 45): 4600,2750 4730,2620 5070,2620 5200,2750 5200,3300 4900,3600 4900,4700 5200,5000 5200,6200 5460,6460 6290,6460 6325,6425 6325,6275 6375,6225 6525,6225 6575,6275 6575,6425 6610,6460 9725,6460 9960,6225 10455,6225 10595,6365 10595,6935 10455,7075 5225,7075 4600,6450

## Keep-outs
Top Layer:
  circle w50: c10950,3650 r104
  circle w10: c6260,4593 r120
  circle w10: c6261,6599.87 r120
  circle w10: c9860,4603 r120
  circle w10: c9860,6609.87 r120
  circle w50: c6150,3340 r104
  circle w50: c9665,3260 r104
  circle w50: c10950,3240 r104
  circle w50: c4760,2435 r135
  circle w50: c11475,2435 r135
  circle w50: c4750,6900 r135
  circle w50: c11485,6890 r135
  circle w50: c6150,4245 r104
  circle w50: c9665,3775 r104
Bottom Layer:
  circle w50: c10950,3650 r104
  circle w10: c6260,4593 r120
  circle w10: c6261,6600 r120
  circle w10: c9860,6610 r120
  circle w10: c9860,4603 r120
  circle w50: c6150,3340 r104
  circle w50: c9665,3260 r104
  circle w50: c10950,3240 r104
  circle w50: c4760,2435 r135
  circle w50: c11475,2435 r135
  circle w50: c4750,6900 r135
  circle w50: c11485,6890 r135
  circle w20: c8031,6910 r100
  circle w20: c8031,6710 r100
  circle w20: c8307,6710 r100
  circle w20: c8307,6910 r100
  circle w50: c6150,4245 r104
  circle w50: c9665,3775 r104
Keep-Out Layer:
  the board outline again, w10

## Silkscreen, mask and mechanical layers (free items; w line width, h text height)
Top Overlay:
  text "GEPE-0138" at 7885,4385 h100
  text "FULL - BRIDGE" at 7685.06,4160 h100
